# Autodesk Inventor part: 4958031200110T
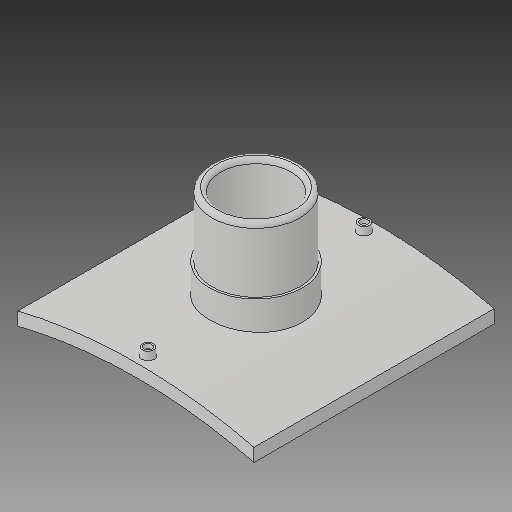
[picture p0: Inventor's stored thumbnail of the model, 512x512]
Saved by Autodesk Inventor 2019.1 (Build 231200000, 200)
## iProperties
Created: 2017-10
Part Number: 4958031200110T
Material: Generic
Description: PLASSON BRANCH SADDLE  1200x110
Document SubType Name: Modeling
Designer: KIM
Mass: 2754.05 g
Surface Area: 3037.44 cm^2
Volume: 2754.05 cm^3
Density: 1 g/cm^3
Appearance: Default
Author: KIM
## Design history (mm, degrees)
derived "495803.ipt"
feature "Solid1::495803.ipt"
tag "TaggingFeature1"
body "Solid1"
other parameters: "d1" = 16, "d2" = 295, "d4" = 0, "d12" = 625.6, "d13" = 14, "d14" = 135, "d16" = 5 deg, "d18" = 4, "d19" = 14, "d20" = 0, "d21" = 3, "d22" = 0, "d23" = 731, "d24" = 115.5, "d25" = 16, "d26" = 88, "d28" = 0, "d29" = 9.6, "d31" = 0, "d32" = 57.5, "d33" = 0, "d34" = 12, "d37" = 80.5, "d38" = 0, "d39" = 6, "B_" = 295, "H_" = 115, "x_" = 16, "D_" = 16
